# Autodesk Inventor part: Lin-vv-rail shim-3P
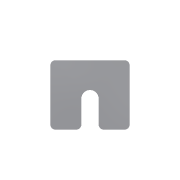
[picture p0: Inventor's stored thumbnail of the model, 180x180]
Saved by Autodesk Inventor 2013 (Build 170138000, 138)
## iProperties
Created: 2012-05
Part Number: Lin-vv-rail shim-3P
Material: Aluminum-6061
Document SubType Name: Modeling
Designer: ssc
Mass: 19.2469 g
Surface Area: 52.7445 cm^2
Volume: 7.10219 cm^3
Density: 2.71 g/cm^3
Author: ssc
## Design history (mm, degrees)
sketch "Sketch1"
  geometry: L1 (3.175, 0)-(16.669, 0); L2 (50.8, 3.175)-(50.8, 41.275); L3 (47.625, 44.45)-(3.175, 44.45); L4 (0, 41.275)-(0, 3.175); L5 (30.956, 3.175)-(30.956, 19.844); L6 (25.4, 25.4)-(25.4, 25.4); L7 (19.844, 19.844)-(19.844, 3.175); L8 (34.131, 0)-(47.625, 0); A1 r 5.556 centre (25.4, 19.844) between (30.956, 19.844) and (25.4, 25.4); A2 r 5.556 centre (25.4, 19.844) between (25.4, 25.4) and (19.844, 19.844); A3 r 3.175 centre (47.625, 3.175) between (47.625, 0) and (50.8, 3.175); A4 r 3.175 centre (47.625, 41.275) between (50.8, 41.275) and (47.625, 44.45); A5 r 3.175 centre (3.175, 41.275) between (3.175, 44.45) and (0, 41.275); A6 r 3.175 centre (3.175, 3.175) between (0, 3.175) and (3.175, 0); A7 r 3.175 centre (16.669, 3.175) between (16.669, 0) and (19.844, 3.175); A8 r 3.175 centre (34.131, 3.175) between (30.956, 3.175) and (34.131, 0); 3 further points
  constraints: 17 tangent, 16 end point, 16 point on circle, 8 centre point, 7 point on line, 4 equal radius, 4 perpendicular, 3 parallel, 1 horizontal, 1 other
  dimensions: "d0" = 44.45 distance of point (0, 44.45) point (0, 0); "d1" = 50.8 distance of point (50.8, 44.45) point (0, 44.45); "d2" = 11.1125 distance between parallel lines of L5 L7; "d3" = 19.84375 distance between parallel lines of L7 L4; "d4" = 25.4 distance between parallel lines of L1 L6; "d5" = 5.55625 radius of A1; "d6" = 3.175 radius of A3; "d7" = 3.175 radius of A7; "d8" = 3.175 radius of A8
extrude "Extrusion1" new body sketch "Sketch1" distance "d9" = 3.175; taper "d10" = 0 deg
body "Solid1"
